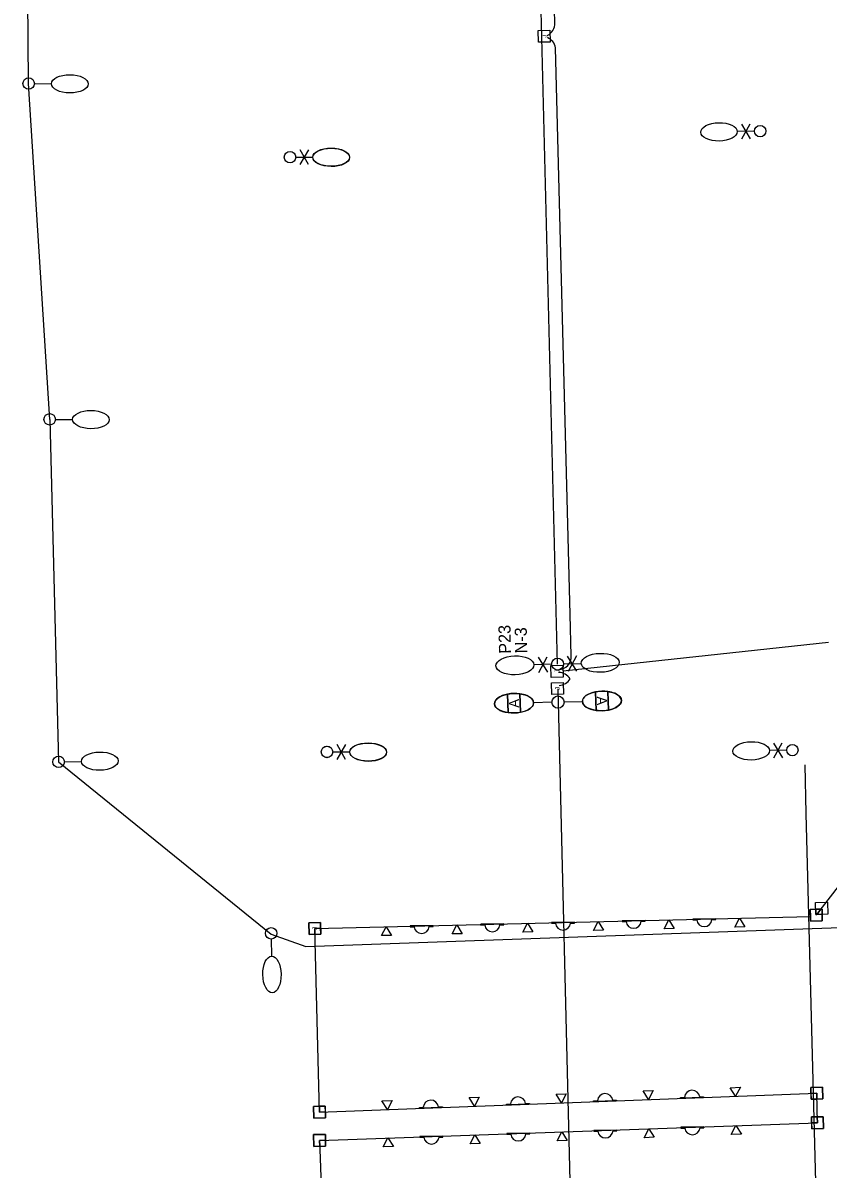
# Model space of a CAD drawing. Extents: x 925407 to 930994, y 604905 to 637063.
# Drawn here: x 929594.6 to 929927.5, y 610501.6 to 610975.5 of the extents above; entities that cross this region are included whole.
import ezdxf

# ---------------------------------------------------------------- set-up
doc = ezdxf.new("R2010")
doc.units = 0
for name, color, linetype in [('ActivePointCell_dp', 7, 'Continuous'), ('Conduit', 7, 'Continuous'), ('ConduitDB', 7, 'Continuous'), ('ConduitJB', 7, 'Continuous'), ('ConduitOT', 7, 'Continuous'), ('GPKDrCellIns_dp', 7, 'Continuous'), ('LightingMisc', 7, 'Continuous'), ('LiteCond_ep', 7, 'Continuous'), ('Miscellaneous2', 7, 'Continuous'), ('Miscellaneous9', 7, 'Continuous'), ('PoleLight', 7, 'Continuous'), ('PoleLight_ep', 7, 'Continuous'), ('PullBox', 7, 'Continuous')]:
    doc.layers.add(name, color=color, linetype=linetype)

msp = doc.modelspace()

# ---------------------------------------------------------------- linework, layer by layer
at = {"layer": 'Conduit'}
for p, q in [((929597.01, 610950.4), (929595.71, 611090.79)), ((929605.72, 610811.59), (929597.01, 610950.4)), ((929605.72, 610811.59), (929609.4, 610669.96)), ((929822.99, 610409.48), (929815.93, 610700.2)), ((929609.4, 610669.96), (929697.26, 610598.74)), ((929711.58, 610593.62), (929936.49, 610601.64)), ((929697.26, 610598.74), (929711.58, 610593.62))]:
    msp.add_line(p, q, dxfattribs=at)
at = {"layer": 'ConduitDB'}
for p, q in [((929927.69, 610719.34), (929817.94, 610707.47)), ((929922.8, 610606.91), (929934.22, 610621.53))]:
    msp.add_line(p, q, dxfattribs=at)
at = {"layer": 'ConduitJB'}
for p, q in [((929715.31, 610601.13), (929920.23, 610606.11)), ((929717.26, 610525.22), (929715.31, 610601.13)), ((929717.26, 610525.22), (929922.81, 610533)), ((929923.12, 610520.82), (929922.81, 610533)), ((929717.31, 610513.51), (929923.12, 610520.82)), ((929717.31, 610513.51), (929719.84, 610435.81))]:
    msp.add_line(p, q, dxfattribs=at)
at = {"layer": 'ConduitOT'}
for p, q in [((929814.59, 610975.47), (929814.24, 610989.04)), ((929820.91, 610730.97), (929814.85, 610965.23)), ((929821.35, 610713.85), (929820.91, 610730.97))]:
    msp.add_line(p, q, dxfattribs=at)
for centre, start, end in [((929809.09, 610975.27), 295.1231, 2.0908), ((929809.43, 610964.29), 9.8429, 68.4434), ((929815.85, 610713.58), 272.6865, 2.8393), ((929816.15, 610701.45), 31.5903, 90.2648), ((929816.06, 610707.06), 272.6865, 330.2317)]:
    msp.add_arc(centre, 5.5, start, end, dxfattribs=at)
at = {"layer": 'GPKDrCellIns_dp'}
for p, q in [((929918.49, 610648.7), (929917.98, 610668.7)), ((929918.49, 610648.7), (929917.98, 610668.7)), ((929924.78, 610404.78), (929918.49, 610648.7)), ((929924.78, 610404.78), (929918.49, 610648.7))]:
    msp.add_line(p, q, dxfattribs=at)
at = {"layer": 'LightingMisc'}
for p, q in [((929851.88, 610604.4), (929842.36, 610604.27)), ((929842.36, 610604.27), (929842.36, 610603.95)), ((929842.36, 610603.95), (929843.96, 610603.98)), ((929850.28, 610604.06), (929851.88, 610604.08)), ((929851.88, 610604.08), (929851.88, 610604.4)), ((929881.09, 610605.11), (929871.57, 610604.98)), ((929871.57, 610604.98), (929871.57, 610604.66)), ((929871.57, 610604.66), (929873.18, 610604.68)), ((929879.49, 610604.77), (929881.09, 610604.79)), ((929881.09, 610604.79), (929881.09, 610605.11)), ((929764.24, 610602.27), (929754.73, 610602.14)), ((929754.73, 610602.14), (929754.73, 610601.83)), ((929754.73, 610601.83), (929756.33, 610601.85)), ((929762.65, 610601.93), (929764.25, 610601.95)), ((929764.25, 610601.95), (929764.24, 610602.27)), ((929793.45, 610602.98), (929783.94, 610602.85)), ((929783.94, 610602.85), (929783.94, 610602.53)), ((929783.94, 610602.53), (929785.54, 610602.56)), ((929791.86, 610602.64), (929793.46, 610602.66)), ((929793.46, 610602.66), (929793.45, 610602.98)), ((929822.67, 610603.69), (929813.15, 610603.56)), ((929813.15, 610603.56), (929813.15, 610603.24)), ((929813.15, 610603.24), (929814.75, 610603.27)), ((929821.07, 610603.35), (929822.67, 610603.37)), ((929822.67, 610603.37), (929822.67, 610603.69)), ((929794.57, 610528.51), (929796.17, 610528.56)), ((929794.57, 610528.2), (929794.57, 610528.51)), ((929804.09, 610528.45), (929794.57, 610528.2)), ((929802.48, 610528.73), (929804.08, 610528.77)), ((929804.08, 610528.77), (929804.09, 610528.45)), ((929830.54, 610529.88), (929832.14, 610529.92)), ((929830.55, 610529.56), (929830.54, 610529.88)), ((929840.06, 610529.81), (929830.55, 610529.56)), ((929838.45, 610530.09), (929840.06, 610530.13)), ((929840.06, 610530.13), (929840.06, 610529.81)), ((929866.51, 610531.23), (929868.12, 610531.27)), ((929866.52, 610530.91), (929866.51, 610531.23)), ((929876.04, 610531.17), (929866.52, 610530.91)), ((929874.43, 610531.44), (929876.03, 610531.49)), ((929876.03, 610531.49), (929876.04, 610531.17)), ((929758.56, 610527.15), (929760.16, 610527.19)), ((929758.57, 610526.83), (929758.56, 610527.15)), ((929768.08, 610527.09), (929758.57, 610526.83)), ((929766.47, 610527.36), (929768.07, 610527.41)), ((929768.07, 610527.41), (929768.08, 610527.09)), ((929876.17, 610519.05), (929866.66, 610518.92)), ((929866.66, 610518.92), (929866.66, 610518.6)), ((929874.58, 610518.71), (929876.18, 610518.73)), ((929876.18, 610518.73), (929876.17, 610519.05)), ((929768.27, 610515.22), (929758.76, 610515.09)), ((929758.76, 610515.09), (929758.76, 610514.77)), ((929758.76, 610514.77), (929760.36, 610514.79)), ((929766.68, 610514.88), (929768.28, 610514.9)), ((929768.28, 610514.9), (929768.27, 610515.22)), ((929804.22, 610516.49), (929794.7, 610516.36)), ((929794.7, 610516.36), (929794.7, 610516.05)), ((929794.7, 610516.05), (929796.31, 610516.07)), ((929802.62, 610516.15), (929804.22, 610516.17)), ((929804.22, 610516.17), (929804.22, 610516.49)), ((929840.2, 610517.77), (929830.68, 610517.64)), ((929830.68, 610517.64), (929830.68, 610517.32)), ((929830.68, 610517.32), (929832.28, 610517.34)), ((929838.6, 610517.43), (929840.2, 610517.45)), ((929840.2, 610517.45), (929840.2, 610517.77)), ((929866.66, 610518.6), (929868.26, 610518.62))]:
    msp.add_line(p, q, dxfattribs=at)
for points in [[(929834.71, 610600.38), (929830.49, 610600.28), (929832.51, 610603.98)], [(929863.92, 610601.09), (929859.7, 610600.99), (929861.72, 610604.69)], [(929893.13, 610601.8), (929888.91, 610601.7), (929890.93, 610605.4)], [(929747.08, 610598.25), (929742.86, 610598.15), (929744.88, 610601.85)], [(929776.29, 610598.96), (929772.07, 610598.86), (929774.09, 610602.56)], [(929805.5, 610599.67), (929801.28, 610599.57), (929803.3, 610603.27)], [(929851.05, 610533.93), (929855.26, 610534.09), (929853.29, 610530.36)], [(929887.02, 610535.29), (929891.24, 610535.45), (929889.27, 610531.72)], [(929743.07, 610529.85), (929747.29, 610530.01), (929745.32, 610526.28)], [(929779.08, 610531.21), (929783.3, 610531.37), (929781.33, 610527.64)], [(929815.07, 610532.58), (929819.29, 610532.74), (929817.32, 610529.01)], [(929891.65, 610516.05), (929887.43, 610515.89), (929889.4, 610519.62)], [(929747.79, 610510.94), (929743.57, 610510.78), (929745.54, 610514.51)], [(929783.73, 610512.22), (929779.52, 610512.06), (929781.49, 610515.79)], [(929819.69, 610513.49), (929815.48, 610513.34), (929817.45, 610517.07)], [(929855.67, 610514.77), (929851.46, 610514.61), (929853.43, 610518.34)]]:
    msp.add_lwpolyline(points, close=True, dxfattribs=at)
for centre, start, end in [((929847.12, 610604.34), 186.5145, 355.0361), ((929876.33, 610605.04), 186.5145, 355.0361), ((929759.48, 610602.21), 186.5145, 355.0361), ((929788.7, 610602.92), 186.5145, 355.0361), ((929817.91, 610603.63), 186.5145, 355.0361), ((929871.28, 610531.04), 7.2789, 175.8005), ((929763.32, 610526.96), 7.2789, 175.8005), ((929799.33, 610528.32), 7.2789, 175.8005), ((929835.31, 610529.69), 7.2789, 175.8005), ((929871.41, 610518.98), 186.5145, 355.0361), ((929763.52, 610515.15), 186.5145, 355.0361), ((929799.46, 610516.43), 186.5145, 355.0361), ((929835.44, 610517.7), 186.5145, 355.0361)]:
    msp.add_arc(centre, 3.17, start, end, dxfattribs=at)
at = {"layer": 'LiteCond_ep'}
for p, q in [((929815.68, 610710.4), (929808.33, 611001.71)), ((929922.38, 610609.05), (929920.16, 610608.99)), ((929924.52, 610609.11), (929922.38, 610609.05)), ((929922.44, 610606.9), (929922.38, 610609.05)), ((929922.38, 610609.05), (929922.44, 610606.9)), ((929922.8, 610606.91), (929924.52, 610609.11)), ((929924.52, 610609.11), (929922.8, 610606.91)), ((929925, 610609.12), (929924.52, 610609.11)), ((929925.05, 610606.96), (929925, 610609.12)), ((929920.28, 610604.15), (929925.12, 610604.27)), ((929922.44, 610606.9), (929922.8, 610606.91)), ((929922.8, 610606.91), (929925.05, 610606.96)), ((929925.12, 610604.27), (929925.05, 610606.96)), ((929717.67, 610603.62), (929712.82, 610603.49)), ((929712.82, 610603.49), (929712.95, 610598.65)), ((929715.31, 610601.13), (929717.73, 610601.19)), ((929717.73, 610601.19), (929715.31, 610601.13)), ((929715.37, 610598.71), (929715.31, 610601.13)), ((929715.31, 610601.13), (929715.37, 610598.71)), ((929717.73, 610601.19), (929717.67, 610603.62)), ((929717.79, 610598.77), (929717.73, 610601.19)), ((929712.95, 610598.65), (929715.37, 610598.71)), ((929715.37, 610598.71), (929717.79, 610598.77)), ((929925.17, 610535.48), (929920.32, 610535.36)), ((929920.32, 610535.36), (929920.39, 610532.91)), ((929920.39, 610532.91), (929922.81, 610533)), ((929922.81, 610533), (929920.39, 610532.91)), ((929920.39, 610532.91), (929920.45, 610530.51)), ((929922.81, 610533), (929922.87, 610530.58)), ((929922.87, 610530.58), (929922.81, 610533)), ((929925.29, 610530.64), (929925.17, 610535.48)), ((929920.45, 610530.51), (929922.87, 610530.58)), ((929922.87, 610530.58), (929925.29, 610530.64)), ((929717.2, 610527.64), (929714.77, 610527.58)), ((929714.77, 610527.58), (929714.9, 610522.73)), ((929719.62, 610527.7), (929717.2, 610527.64)), ((929717.26, 610525.22), (929717.2, 610527.64)), ((929717.2, 610527.64), (929717.26, 610525.22)), ((929719.68, 610525.31), (929717.26, 610525.22)), ((929717.26, 610525.22), (929719.68, 610525.31)), ((929719.68, 610525.31), (929719.62, 610527.7)), ((929719.74, 610522.86), (929719.68, 610525.31)), ((929714.9, 610522.73), (929719.74, 610522.86)), ((929923.06, 610523.24), (929920.64, 610523.18)), ((929920.64, 610523.18), (929920.7, 610520.73)), ((929923.12, 610520.82), (929920.7, 610520.73)), ((929920.7, 610520.73), (929923.12, 610520.82)), ((929920.7, 610520.73), (929920.76, 610518.33)), ((929925.48, 610523.3), (929923.06, 610523.24)), ((929923.06, 610523.24), (929923.12, 610520.82)), ((929923.12, 610520.82), (929923.06, 610523.24)), ((929925.6, 610518.46), (929925.48, 610523.3)), ((929719.67, 610516), (929714.82, 610515.87)), ((929714.82, 610515.87), (929714.95, 610511.03)), ((929719.73, 610513.6), (929719.67, 610516)), ((929920.76, 610518.33), (929925.6, 610518.46)), ((929714.95, 610511.03), (929717.39, 610511.09)), ((929717.31, 610513.51), (929719.73, 610513.6)), ((929719.73, 610513.6), (929717.31, 610513.51)), ((929717.39, 610511.09), (929717.31, 610513.51)), ((929717.31, 610513.51), (929717.39, 610511.09)), ((929717.39, 610511.09), (929719.79, 610511.15)), ((929719.79, 610511.15), (929719.73, 610513.6))]:
    msp.add_line(p, q, dxfattribs=at)
for points in [[(929920.16, 610608.99), (929920.23, 610606.11), (929920.28, 610604.15)], [(929925.05, 610606.96), (929922.8, 610606.91), (929922.44, 610606.9)]]:
    msp.add_lwpolyline(points, dxfattribs=at)
at = {"layer": 'Miscellaneous2'}
for p, q in [((929831.37, 610698.94), (929831.37, 610698.94)), ((929831.37, 610698.94), (929831.57, 610691.28)), ((929836.67, 610691.41), (929836.47, 610699.07)), ((929836.47, 610699.07), (929836.47, 610699.07)), ((929795.03, 610698.01), (929795.03, 610698.01)), ((929795.03, 610698.01), (929795.23, 610690.34)), ((929800.33, 610690.48), (929800.13, 610698.14)), ((929800.13, 610698.14), (929800.13, 610698.14))]:
    msp.add_line(p, q, dxfattribs=at)
for centre, start_param, end_param in [((929834.02, 610695.18), 1.249648, 1.891946), ((929797.68, 610694.24), 1.249648, 1.891946), ((929797.68, 610694.24), 4.391271, 5.033538), ((929797.68, 610694.24), 4.391241, 4.391271), ((929834.02, 610695.18), 4.391271, 5.033538), ((929834.02, 610695.18), 4.391241, 4.391271)]:
    msp.add_ellipse(centre, major_axis=(8.08, 0.21), ratio=0.5, start_param=start_param, end_param=end_param, dxfattribs=at)
at = {"layer": 'PoleLight'}
for p, q in [((929831.57, 610691.28), (929831.37, 610698.94)), ((929836.47, 610699.07), (929836.67, 610691.41)), ((929795.23, 610690.34), (929795.03, 610698.01)), ((929800.13, 610698.14), (929800.33, 610690.48)), ((929813.33, 610694.64), (929805.76, 610694.45)), ((929818.37, 610694.77), (929825.94, 610694.97))]:
    msp.add_line(p, q, dxfattribs=at)
msp.add_circle((929815.85, 610694.71), 2.52, dxfattribs=at)
msp.add_circle((929815.85, 610694.71), 2.52, dxfattribs=at)
for centre in [(929834.02, 610695.18), (929797.68, 610694.24)]:
    msp.add_ellipse(centre, major_axis=(8.08, 0.21), ratio=0.5, dxfattribs=at)
for centre, start_param, end_param in [((929834.02, 610695.18), 1.891945, 4.391241), ((929834.02, 610695.18), 0.847605, 1.249648), ((929797.68, 610694.24), 1.891945, 4.391241), ((929797.68, 610694.24), 0.847605, 1.249648), ((929797.68, 610694.24), 5.033538, 6.283185), ((929797.68, 610694.24), 0, 0.847605), ((929834.02, 610695.18), 5.033538, 6.283185), ((929834.02, 610695.18), 0, 0.847605)]:
    msp.add_ellipse(centre, major_axis=(8.08, 0.21), ratio=0.5, start_param=start_param, end_param=end_param, dxfattribs=at)
at = {"layer": 'PoleLight_ep'}
for p, q in [((929599.38, 610950.38), (929606.47, 610950.34)), ((929891.69, 610933.68), (929895.35, 610927.61)), ((929891.8, 610927.54), (929895.24, 610933.75)), ((929897.07, 610930.71), (929889.98, 610930.58)), ((929712.75, 610923.06), (929709.19, 610916.92)), ((929712.74, 610916.92), (929709.2, 610923.06)), ((929707.42, 610919.99), (929714.52, 610919.99)), ((929707.42, 610919.98), (929714.52, 610919.94)), ((929608.09, 610811.58), (929615.18, 610811.54)), ((929807.71, 610713.31), (929811.57, 610707.06)), ((929807.89, 610706.95), (929811.38, 610713.42)), ((929823.66, 610707.5), (929819.8, 610713.75)), ((929823.47, 610713.86), (929819.99, 610707.39)), ((929813.23, 610710.33), (929805.89, 610710.12)), ((929818.13, 610710.48), (929825.48, 610710.69)), ((929728.03, 610677.15), (929724.48, 610671.01)), ((929728.02, 610671.01), (929724.49, 610677.15)), ((929905.01, 610677.78), (929908.66, 610671.7)), ((929905.12, 610671.64), (929908.55, 610677.85)), ((929722.71, 610674.09), (929729.8, 610674.08)), ((929722.71, 610674.07), (929729.81, 610674.03)), ((929910.38, 610674.81), (929903.29, 610674.68)), ((929611.76, 610670), (929618.86, 610670.13)), ((929697.31, 610596.76), (929697.44, 610589.66))]:
    msp.add_line(p, q, dxfattribs=at)
for centre, radius in [((929597.01, 610950.4), 2.37), ((929899.43, 610930.75), 2.36), ((929705.06, 610920), 2.37), ((929705.06, 610920), 2.36), ((929605.72, 610811.59), 2.37), ((929815.68, 610710.4), 2.45), ((929720.34, 610674.09), 2.37), ((929720.34, 610674.09), 2.36), ((929912.75, 610674.85), 2.36), ((929609.4, 610669.96), 2.37), ((929697.26, 610599.12), 2.37)]:
    msp.add_circle(centre, radius, dxfattribs=at)
for centre, major_axis in [((929614.04, 610950.29), (7.57, -0.05)), ((929882.41, 610930.44), (-7.57, -0.14)), ((929722.08, 610919.98), (7.57, -0.01)), ((929722.09, 610919.89), (7.57, -0.05)), ((929622.75, 610811.49), (7.57, -0.05)), ((929798.05, 610709.88), (-7.84, -0.23)), ((929833.32, 610710.93), (7.84, 0.23)), ((929737.38, 610673.98), (7.57, -0.05)), ((929737.37, 610674.07), (7.57, -0.01)), ((929895.72, 610674.54), (-7.57, -0.14)), ((929626.43, 610670.28), (7.57, 0.14)), ((929697.59, 610582.09), (0.14, -7.57))]:
    msp.add_ellipse(centre, major_axis=major_axis, ratio=0.5, dxfattribs=at)
at = {"layer": 'PullBox'}
for p, q in [((929807.61, 610972.3), (929812.45, 610972.43)), ((929807.73, 610967.46), (929807.61, 610972.3)), ((929812.45, 610972.43), (929812.58, 610967.58)), ((929812.58, 610967.58), (929807.73, 610967.46)), ((929812.88, 610709.84), (929817.87, 610709.97)), ((929813.01, 610704.85), (929812.88, 610709.84)), ((929817.87, 610709.97), (929818, 610704.97)), ((929818, 610704.97), (929813.01, 610704.85)), ((929813.14, 610702.63), (929817.98, 610702.75)), ((929813.26, 610697.79), (929813.14, 610702.63)), ((929817.98, 610702.75), (929818.11, 610697.91)), ((929818.11, 610697.91), (929813.26, 610697.79)), ((929920.16, 610608.99), (929925, 610609.12)), ((929920.28, 610604.15), (929920.16, 610608.99)), ((929922.31, 610611.9), (929927.31, 610612.02)), ((929922.44, 610606.9), (929922.31, 610611.9)), ((929925, 610609.12), (929925.12, 610604.27)), ((929927.31, 610612.02), (929927.44, 610607.03)), ((929925.12, 610604.27), (929920.28, 610604.15)), ((929927.44, 610607.03), (929922.44, 610606.9)), ((929712.82, 610603.49), (929717.67, 610603.62)), ((929712.95, 610598.65), (929712.82, 610603.49)), ((929717.67, 610603.62), (929717.79, 610598.77)), ((929717.79, 610598.77), (929712.95, 610598.65)), ((929920.32, 610535.36), (929925.17, 610535.48)), ((929920.45, 610530.51), (929920.32, 610535.36)), ((929925.17, 610535.48), (929925.29, 610530.64)), ((929925.29, 610530.64), (929920.45, 610530.51)), ((929714.77, 610527.58), (929719.62, 610527.7)), ((929714.9, 610522.73), (929714.77, 610527.58)), ((929719.62, 610527.7), (929719.74, 610522.86)), ((929719.74, 610522.86), (929714.9, 610522.73)), ((929920.64, 610523.18), (929925.48, 610523.3)), ((929920.76, 610518.33), (929920.64, 610523.18)), ((929925.48, 610523.3), (929925.6, 610518.46)), ((929714.82, 610515.87), (929719.67, 610516)), ((929714.95, 610511.03), (929714.82, 610515.87)), ((929719.67, 610516), (929719.79, 610511.15)), ((929925.6, 610518.46), (929920.76, 610518.33)), ((929719.79, 610511.15), (929714.95, 610511.03))]:
    msp.add_line(p, q, dxfattribs=at)

# ---------------------------------------------------------------- texts
at = {"layer": 'ActivePointCell_dp'}
for s, p in [('P23', (929796.44, 610714.74)), ('N-3', (929803.14, 610714.88))]:
    msp.add_text(s, height=5, rotation=91.1767, dxfattribs=at).set_placement(p)
at = {"layer": 'Miscellaneous9'}
for rotation, p in [(91.4757, (929799.77, 610692.39)), (271.4757, (929831.93, 610697.02))]:
    msp.add_text('A', height=4.08, rotation=rotation, dxfattribs=at).set_placement(p)
at = {"layer": 'PullBox'}
for height, p in [(1.94, (929811.08, 610969.31)), (2, (929816.46, 610706.76)), (1.94, (929816.61, 610699.64)), (1.94, (929716.29, 610600.5))]:
    msp.add_text('J', height=height, rotation=91.4756, dxfattribs=at).set_placement(p)

doc.saveas('drawing.dxf')
